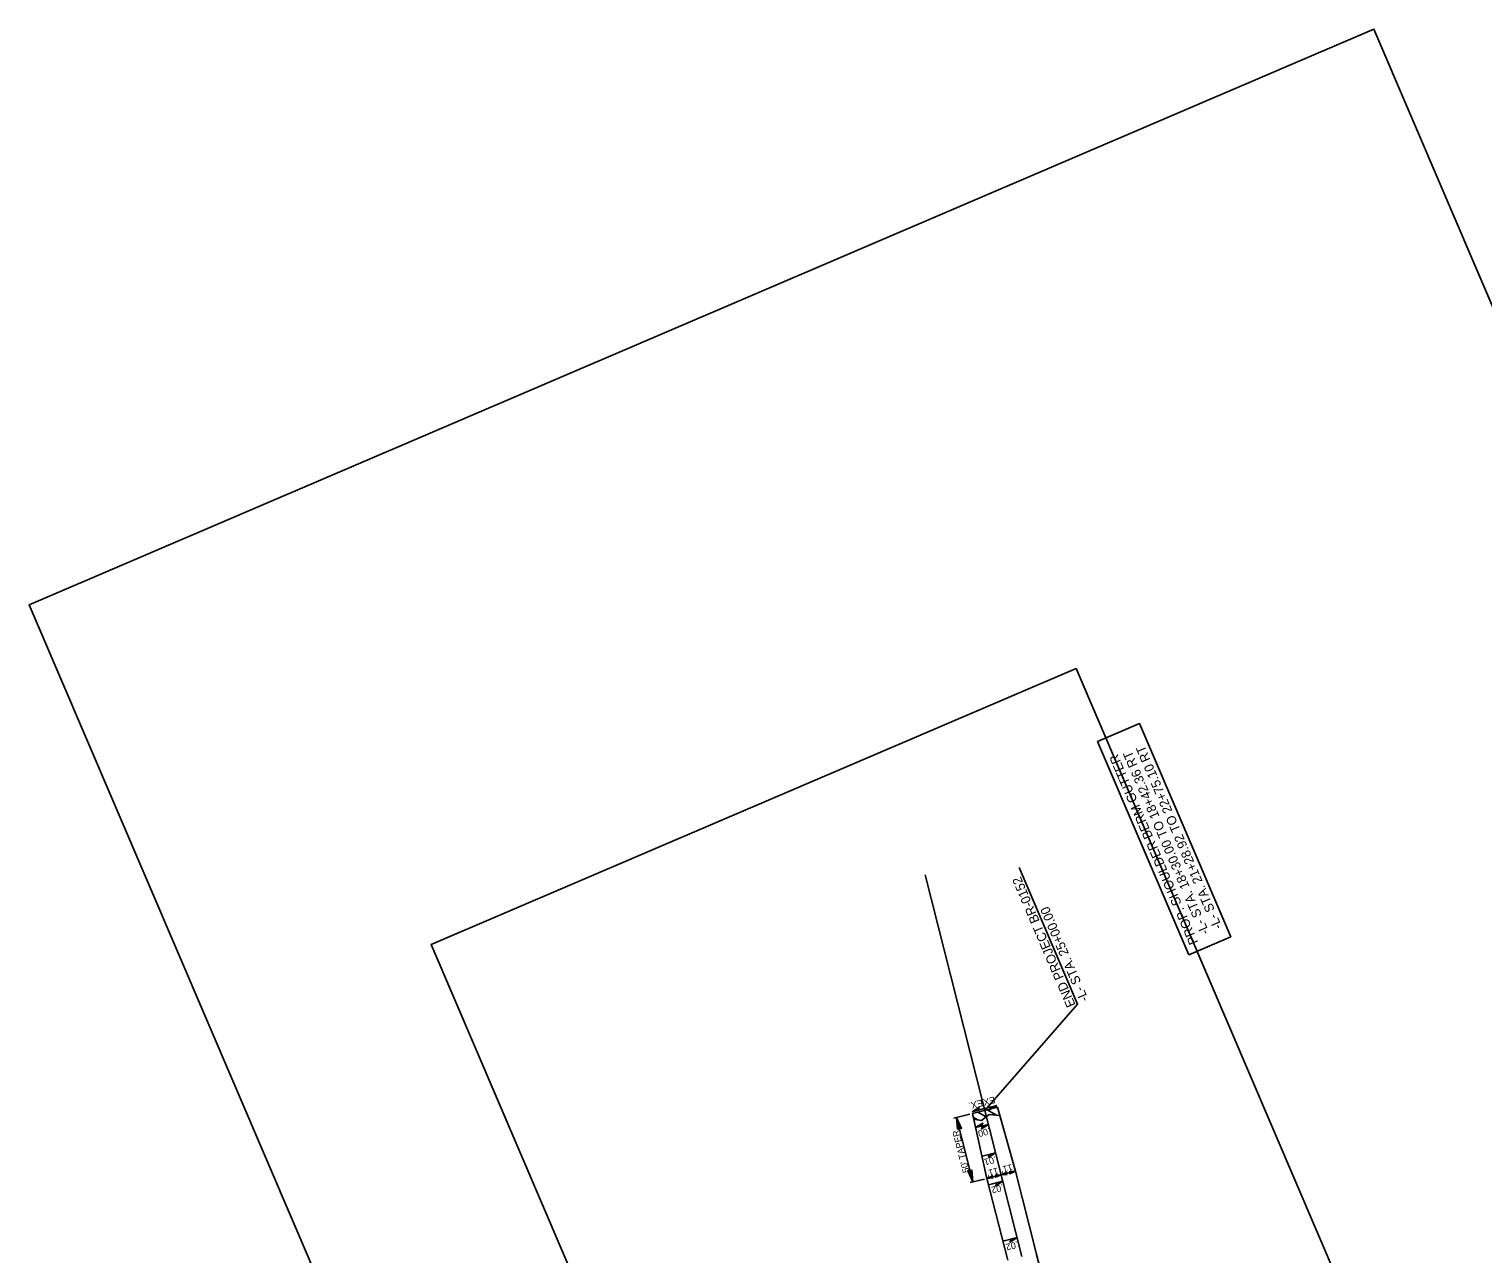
# Model space of a CAD drawing. Extents: x 1550950 to 1552827, y 809595 to 812050.
# Drawn here: x 1550950 to 1552043, y 811130 to 812050 of the extents above; entities that cross this region are included whole.
import ezdxf

# ---------------------------------------------------------------- set-up
doc = ezdxf.new("R2010")
doc.units = 0
for name, color, linetype in [('3D Cell Connection Region', 7, 'Continuous'), ('_CIVIL_CONSTRUCTION', 7, 'Continuous'), ('Catch Basin Box 24 Dia-Bottom CELL', 7, 'Continuous'), ('Draft_Plan_Labels', 7, 'Continuous'), ('Drop Inlet Grate 2 Narrow Slot and Flat Grates 840 29 36 Dia BD Apron CELL', 7, 'Continuous'), ('Drop Inlet Grate 2 Narrow Slot and Flat Grates 840 29 36 Dia BD CELL', 7, 'Continuous'), ('Drop Inlet Grate 2 Narrow Slot and Flat Grates 840 29 36 Dia TB-Top CELL', 7, 'Continuous'), ('Drop Inlet Grate 840 16 CELL', 7, 'Continuous'), ('P_HYD_Drop_Inlet_Box_Traffic_Bearing_840_35-Bottom_CELL', 7, 'Continuous'), ('P_HYD_Pipe_RCP_15in_Class_III', 7, 'Continuous'), ('V Ditch Special Lateral with PSRM Detail CELL', 7, 'Continuous')]:
    doc.layers.add(name, color=color, linetype=linetype)

msp = doc.modelspace()

# ---------------------------------------------------------------- linework, layer by layer
at = {"layer": '3D Cell Connection Region'}
for p, q in [((1551659.3, 811236.5), (1551668.6, 811238.8)), ((1551677.9, 811241.2), (1551668.6, 811238.8)), ((1551662, 811224.5), (1551671.6, 811226.9)), ((1551666.8, 811203), (1551677, 811205.6)), ((1551671.8, 811181.5), (1551682.4, 811184.2)), ((1551682.5, 811139.1), (1551693.2, 811141.8))]:
    msp.add_line(p, q, dxfattribs=at)
at = {"layer": '_CIVIL_CONSTRUCTION'}
for p, q in [((1551645.6, 811231.6), (1551657.7, 811234.7)), ((1551659.9, 811183.7), (1551647.6, 811232.1)), ((1551670.5, 811186.4), (1551681.2, 811189.1)), ((1551681.2, 811189.1), (1551691.9, 811191.8)), ((1551657.9, 811183.2), (1551668.6, 811185.9))]:
    msp.add_line(p, q, dxfattribs=at)
at = {"layer": 'Draft_Plan_Labels'}
msp.add_lwpolyline([(1551822.3, 811354.5), (1551753.7, 811514.8), (1551785.2, 811528.3), (1551853.8, 811368)], close=True, dxfattribs=at)
msp.add_lwpolyline([(1551668.9, 811237.5), (1551738.7, 811317.4), (1551694.8, 811420)], dxfattribs=at)
at = {"layer": 'Drop Inlet Grate 2 Narrow Slot and Flat Grates 840 29 36 Dia BD Apron CELL'}
for p, q in [((1551669.9, 811232.6), (1551663.6, 811236.2)), ((1551677.8, 811233.9), (1551670.6, 811238)), ((1551678.7, 811239.1), (1551677.6, 811239.7)), ((1551663.5, 811230.5), (1551660.2, 811232.3))]:
    msp.add_line(p, q, dxfattribs=at)
msp.add_lwpolyline([(1551660.5, 811231), (1551666.5, 811229.9), (1551672.1, 811234.3), (1551680.2, 811233.7)], dxfattribs=at)
at = {"layer": 'Drop Inlet Grate 2 Narrow Slot and Flat Grates 840 29 36 Dia BD CELL'}
msp.add_lwpolyline([(1551862.1, 809937.1), (1551252.5, 811362.2), (1551737.5, 811569.6), (1552347.1, 810144.5)], close=True, dxfattribs=at)
at = {"layer": 'Drop Inlet Grate 2 Narrow Slot and Flat Grates 840 29 36 Dia TB-Top CELL'}
for points in [[(1551648.3, 811223), (1551647.6, 811232.1), (1551651.3, 811223.8), (1551649.5, 811224.5)], [(1551659.2, 811192.8), (1551659.9, 811183.7), (1551656.1, 811192.1), (1551657.9, 811191.3)], [(1551676.6, 811188.7), (1551681.2, 811189.1), (1551677, 811187.2), (1551677.4, 811188.1)], [(1551685.7, 811189.4), (1551681.2, 811189.1), (1551685.4, 811191), (1551685, 811190.1)], [(1551687.3, 811191.4), (1551691.9, 811191.8), (1551687.7, 811189.9), (1551688, 811190.8)], [(1551675.1, 811186.7), (1551670.5, 811186.4), (1551674.7, 811188.3), (1551674.4, 811187.4)]]:
    msp.add_lwpolyline(points, close=True, dxfattribs=at)
at = {"layer": 'Drop Inlet Grate 840 16 CELL'}
for points in [[(1551659.3, 811236.5), (1551664.6, 811239.9), (1551663.8, 811237.6)], [(1551677.9, 811241.2), (1551672.5, 811237.8), (1551673.4, 811240)], [(1551662, 811224.5), (1551667.3, 811227.9), (1551666.5, 811225.6)], [(1551671.6, 811226.9), (1551666.3, 811223.5), (1551667.1, 811225.7)], [(1551677, 811205.6), (1551671.7, 811202.1), (1551672.5, 811204.4)], [(1551682.4, 811184.2), (1551677.1, 811180.8), (1551677.9, 811183.1)], [(1551693.2, 811141.8), (1551687.9, 811138.4), (1551688.7, 811140.6)]]:
    msp.add_lwpolyline(points, close=True, dxfattribs=at)
at = {"layer": 'P_HYD_Pipe_RCP_15in_Class_III'}
msp.add_line((1551696.8, 811127.6), (1551624, 811414.6), dxfattribs=at)
msp.add_lwpolyline([(1552827.2, 810027.9), (1551961.5, 812050.4), (1550950.2, 811617.6), (1551815.9, 809595.1)], close=True, dxfattribs=at)
at = {"layer": 'V Ditch Special Lateral with PSRM Detail CELL'}
for p, q in [((1551659.6, 811235.2), (1551678.4, 811240)), ((1551670.5, 811186.4), (1551659.6, 811235.2)), ((1551678.4, 811240), (1551691.9, 811191.8)), ((1551707.5, 811130.3), (1551691.9, 811191.8)), ((1551686.2, 811124.8), (1551670.5, 811186.4))]:
    msp.add_line(p, q, dxfattribs=at)
msp.add_arc((1554524.2, 811845.1), 2906, 194.2411, 210.6719, dxfattribs=at)

# ---------------------------------------------------------------- texts
at = {"layer": 'Catch Basin Box 24 Dia-Bottom CELL'}
for s, p in [('EX.', (1551666.7, 811245.7)), ('EX.', (1551676, 811248)), ('.00', (1551672.4, 811224.5)), ('.01', (1551676.9, 811203.1)), ('.02', (1551682.4, 811182.1)), ('.02', (1551693.3, 811139.2))]:
    msp.add_text(s, height=5, rotation=194.2411, dxfattribs=at).set_placement(p)
at = {"layer": 'Draft_Plan_Labels'}
for s, p in [('-L- STA. 18+30.00 TO 18+42.36 RT', (1551837.8, 811371.2)), ('-L- STA. 21+28.92 TO 22+75.10 RT', (1551847.5, 811375.3)), ('PROP. SHOULDER BERM GUTTER', (1551829.5, 811363.9)), ('END PROJECT BR-0152', (1551737.3, 811316.8)), ('-L- STA. 25+00.00', (1551747, 811320.9))]:
    msp.add_text(s, height=7, rotation=113.1736, dxfattribs=at).set_placement(p)
at = {"layer": 'P_HYD_Drop_Inlet_Box_Traffic_Bearing_840_35-Bottom_CELL'}
for s, rotation, p in [("50' TAPER", 104.2411, (1551657.4, 811191.2)), ("11'", 194.2411, (1551678.4, 811194.5)), ("11'", 194.2411, (1551689.1, 811197.2))]:
    msp.add_text(s, height=5, rotation=rotation, dxfattribs=at).set_placement(p)

doc.saveas('drawing.dxf')
